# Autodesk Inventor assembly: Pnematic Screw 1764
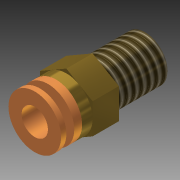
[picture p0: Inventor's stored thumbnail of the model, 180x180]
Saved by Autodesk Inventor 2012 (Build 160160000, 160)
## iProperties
Created: 2010-02
Part Number: Pnematic Screw 1764
Document SubType Name: Assembly
Designer: clee1
Author: clee1
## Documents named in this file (3)
- R:\CAD Archives\Pneumatics_1764\Pneumatic_Screw_1764\Pneumatic_Screw_1764.iam
- R:\CAD Archives\Pneumatics_1764\Pneumatic_Screw_1764\Pneumatic_Screw_Part_1_1764.ipt
- R:\CAD Archives\Pneumatics_1764\Pneumatic_Screw_1764\Pneumatic_Screw_Part _2_1764.ipt
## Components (2 placed, 2 different names)
1. Pneumatic_Screw_Part_1_1764:1 — Insert:1
2. Pneumatic_Screw_Part _2_1764:1 — Insert:1
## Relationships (1: Insert 1)
- Insert:1: Pneumatic_Screw_Part_1_1764:1 ↔ Pneumatic_Screw_Part _2_1764:1
